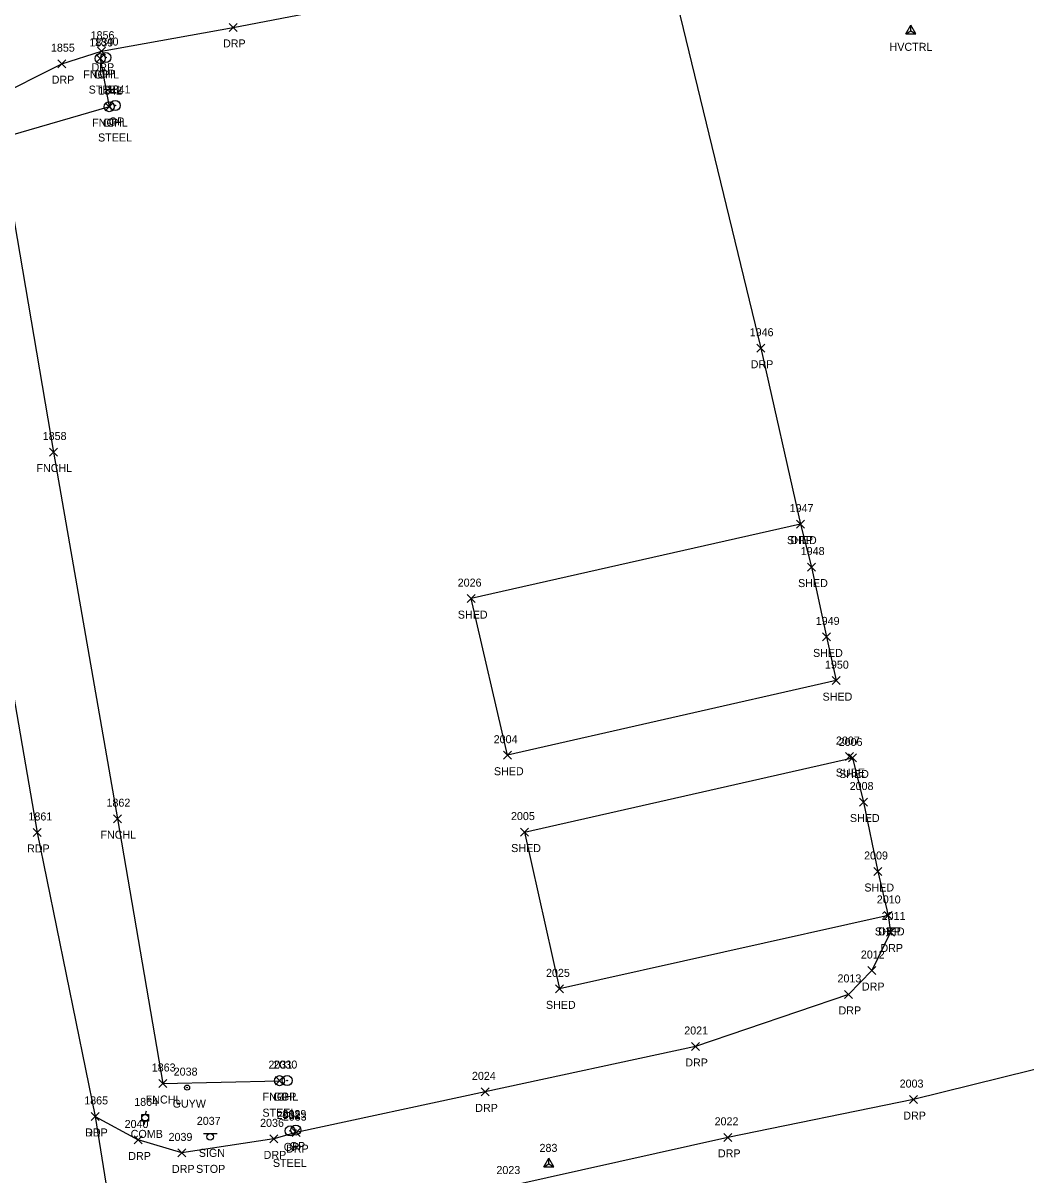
# Model space of a CAD drawing. Extents: x 1481523 to 1489083, y 884156 to 893756.
# Drawn here: x 1486651.1 to 1486901.6, y 888166.7 to 888454.5 of the extents above; entities that cross this region are included whole.
import ezdxf

# ---------------------------------------------------------------- set-up
doc = ezdxf.new("R2010")
doc.units = 0
for name, color, linetype in [('C_A', 7, 'Continuous'), ('C_I', 7, 'Continuous'), ('CPSM', 7, 'Continuous'), ('L_A', 7, 'Continuous'), ('L_I', 7, 'Continuous'), ('L_TIC', 7, 'Continuous'), ('LBC', 7, 'Continuous'), ('LFNC', 7, 'Continuous'), ('P_A', 7, 'Continuous'), ('P_I', 7, 'Continuous'), ('P_TIC', 7, 'Continuous'), ('PET', 7, 'Continuous'), ('R_A', 7, 'Continuous'), ('R_C', 7, 'Continuous'), ('R_I', 7, 'Continuous'), ('R_TIC', 7, 'Continuous'), ('RDP', 7, 'Continuous'), ('RGP', 7, 'Continuous'), ('S_A', 7, 'Continuous'), ('S_C', 7, 'Continuous'), ('S_I', 7, 'Continuous'), ('SSGN', 7, 'Continuous'), ('U_A', 7, 'Continuous'), ('U_I', 7, 'Continuous'), ('U_TIC', 7, 'Continuous'), ('UP', 7, 'Continuous'), ('UPGW', 7, 'Continuous')]:
    doc.layers.add(name, color=color, linetype=linetype)

msp = doc.modelspace()

# ---------------------------------------------------------------- linework, layer by layer
at = {"layer": 'CPSM'}
for p, q in [((1486871.57, 888451.78), (1486872.82, 888453.95)), ((1486874.07, 888451.78), (1486872.82, 888453.95)), ((1486872.82, 888452.51), (1486872.82, 888453.95)), ((1486871.57, 888451.78), (1486872.82, 888452.51)), ((1486871.57, 888451.78), (1486874.07, 888451.78)), ((1486872.82, 888452.51), (1486872.82, 888452.51)), ((1486872.82, 888452.51), (1486874.07, 888451.78)), ((1486781.2, 888168.7), (1486782.45, 888170.86)), ((1486783.7, 888168.7), (1486782.45, 888170.86)), ((1486782.45, 888169.42), (1486782.45, 888170.86)), ((1486781.2, 888168.7), (1486782.45, 888169.42)), ((1486781.2, 888168.7), (1486783.7, 888168.7)), ((1486782.45, 888169.42), (1486782.45, 888169.42)), ((1486782.45, 888169.42), (1486783.7, 888168.7))]:
    msp.add_line(p, q, dxfattribs=at)
at = {"layer": 'L_TIC'}
for points in [[(1486669.36, 888444.6), (1486671.36, 888446.6)], [(1486671.36, 888444.6), (1486669.36, 888446.6)], [(1486671.6, 888432.56), (1486673.6, 888434.56)], [(1486673.6, 888432.56), (1486671.6, 888434.56)], [(1486657.68, 888346.28), (1486659.68, 888348.28)], [(1486659.68, 888346.28), (1486657.68, 888348.28)], [(1486844.25, 888328.26), (1486846.25, 888330.26)], [(1486846.25, 888328.26), (1486844.25, 888330.26)], [(1486844.25, 888328.26), (1486846.25, 888330.26)], [(1486846.25, 888328.26), (1486844.25, 888330.26)], [(1486847.03, 888317.53), (1486849.03, 888319.53)], [(1486849.03, 888317.53), (1486847.03, 888319.53)], [(1486762.04, 888309.65), (1486764.04, 888311.65)], [(1486764.04, 888309.65), (1486762.04, 888311.65)], [(1486762.04, 888309.65), (1486764.04, 888311.65)], [(1486764.04, 888309.65), (1486762.04, 888311.65)], [(1486850.78, 888300.08), (1486852.78, 888302.08)], [(1486852.78, 888300.08), (1486850.78, 888302.08)], [(1486853.16, 888289.15), (1486855.16, 888291.15)], [(1486855.16, 888289.15), (1486853.16, 888291.15)], [(1486771.06, 888270.52), (1486773.06, 888272.52)], [(1486773.06, 888270.52), (1486771.06, 888272.52)], [(1486857.29, 888269.84), (1486859.29, 888271.84)], [(1486859.29, 888269.84), (1486857.29, 888271.84)], [(1486859.98, 888258.83), (1486861.98, 888260.83)], [(1486861.98, 888258.83), (1486859.98, 888260.83)], [(1486673.66, 888254.66), (1486675.66, 888256.66)], [(1486675.66, 888254.66), (1486673.66, 888256.66)], [(1486775.37, 888251.32), (1486777.37, 888253.32)], [(1486777.37, 888251.32), (1486775.37, 888253.32)], [(1486775.37, 888251.32), (1486777.37, 888253.32)], [(1486777.37, 888251.32), (1486775.37, 888253.32)], [(1486863.58, 888241.47), (1486865.58, 888243.47)], [(1486865.58, 888241.47), (1486863.58, 888243.47)], [(1486866.2, 888230.49), (1486868.2, 888232.49)], [(1486868.2, 888230.49), (1486866.2, 888232.49)], [(1486784.05, 888212.15), (1486786.05, 888214.15)], [(1486786.05, 888212.15), (1486784.05, 888214.15)], [(1486784.05, 888212.15), (1486786.05, 888214.15)], [(1486786.05, 888212.15), (1486784.05, 888214.15)], [(1486714.15, 888189.21), (1486716.15, 888191.21)], [(1486716.15, 888189.21), (1486714.15, 888191.21)], [(1486684.97, 888188.5), (1486686.97, 888190.5)], [(1486686.97, 888188.5), (1486684.97, 888190.5)]]:
    msp.add_lwpolyline(points, dxfattribs=at)
at = {"layer": 'LBC'}
for points in [[(1486845.25, 888329.26), (1486848.03, 888318.53), (1486851.78, 888301.08), (1486854.16, 888290.15), (1486772.06, 888271.52), (1486763.04, 888310.65)], [(1486845.25, 888329.26), (1486763.04, 888310.65)], [(1486776.37, 888252.32), (1486858.29, 888270.84), (1486860.98, 888259.83), (1486864.58, 888242.47), (1486867.2, 888231.49), (1486785.05, 888213.15)], [(1486776.37, 888252.32), (1486785.05, 888213.15)]]:
    msp.add_lwpolyline(points, dxfattribs=at)
at = {"layer": 'LFNC'}
msp.add_lwpolyline([(1486670.36, 888445.6), (1486672.6, 888433.56), (1486645.27, 888425.57), (1486658.68, 888347.28), (1486674.66, 888255.66), (1486685.97, 888189.5), (1486715.15, 888190.21)], dxfattribs=at)
at = {"layer": 'P_TIC'}
for points in [[(1486653.61, 888251.22), (1486655.61, 888253.22)], [(1486655.61, 888251.22), (1486653.61, 888253.22)], [(1486668.1, 888180.27), (1486670.1, 888182.27)], [(1486670.1, 888180.27), (1486668.1, 888182.27)]]:
    msp.add_lwpolyline(points, dxfattribs=at)
at = {"layer": 'PET'}
msp.add_lwpolyline([(1486482.46, 889213.8), (1486493.22, 889156.8), (1486512.17, 889057.76), (1486527.58, 888974.51), (1486542.53, 888889.08), (1486553.79, 888825.37), (1486565.07, 888760.91), (1486577.19, 888690.78), (1486591.4, 888610.57), (1486602.78, 888547.25), (1486614.23, 888481.5), (1486627.06, 888409.28), (1486638.94, 888342.58), (1486654.61, 888252.22), (1486669.1, 888181.27), (1486680.17, 888112.03), (1486680.99, 888105.73)], dxfattribs=at)
at = {"layer": 'R_TIC'}
for points in [[(1486702.54, 888452.36), (1486704.54, 888454.36)], [(1486704.54, 888452.36), (1486702.54, 888454.36)], [(1486669.7, 888446.41), (1486671.7, 888448.41)], [(1486671.7, 888446.41), (1486669.7, 888448.41)], [(1486659.74, 888443.3), (1486661.74, 888445.3)], [(1486661.74, 888443.3), (1486659.74, 888445.3)], [(1486834.34, 888372.21), (1486836.34, 888374.21)], [(1486836.34, 888372.21), (1486834.34, 888374.21)], [(1486844.25, 888328.26), (1486846.25, 888330.26)], [(1486846.25, 888328.26), (1486844.25, 888330.26)], [(1486866.2, 888230.49), (1486868.2, 888232.49)], [(1486868.2, 888230.49), (1486866.2, 888232.49)], [(1486866.75, 888226.35), (1486868.75, 888228.35)], [(1486868.75, 888226.35), (1486866.75, 888228.35)], [(1486862.12, 888216.72), (1486864.12, 888218.72)], [(1486864.12, 888216.72), (1486862.12, 888218.72)], [(1486856.29, 888210.76), (1486858.29, 888212.76)], [(1486858.29, 888210.76), (1486856.29, 888212.76)], [(1486818.01, 888197.75), (1486820.01, 888199.75)], [(1486820.01, 888197.75), (1486818.01, 888199.75)], [(1486765.54, 888186.41), (1486767.54, 888188.41)], [(1486767.54, 888186.41), (1486765.54, 888188.41)], [(1486872.46, 888184.48), (1486874.46, 888186.48)], [(1486874.46, 888184.48), (1486872.46, 888186.48)], [(1486668.1, 888180.27), (1486670.1, 888182.27)], [(1486670.1, 888180.27), (1486668.1, 888182.27)], [(1486712.68, 888174.67), (1486714.68, 888176.67)], [(1486714.68, 888174.67), (1486712.68, 888176.67)], [(1486718.3, 888176.23), (1486720.3, 888178.23)], [(1486720.3, 888176.23), (1486718.3, 888178.23)], [(1486826.16, 888175.05), (1486828.16, 888177.05)], [(1486828.16, 888175.05), (1486826.16, 888177.05)], [(1486678.87, 888174.39), (1486680.87, 888176.39)], [(1486680.87, 888174.39), (1486678.87, 888176.39)], [(1486678.87, 888174.39), (1486680.87, 888176.39)], [(1486680.87, 888174.39), (1486678.87, 888176.39)], [(1486689.78, 888171.16), (1486691.78, 888173.16)], [(1486691.78, 888171.16), (1486689.78, 888173.16)]]:
    msp.add_lwpolyline(points, dxfattribs=at)
at = {"layer": 'RDP'}
for points in [[(1486627.06, 888409.28), (1486634.2, 888424.78), (1486643.14, 888435.44), (1486660.74, 888444.3), (1486670.7, 888447.41), (1486703.54, 888453.36), (1486762.17, 888464.63), (1486810.87, 888474.09), (1486835.34, 888373.21), (1486845.25, 888329.26)], [(1486959.85, 888365.95), (1486963.01, 888350.2), (1486966.58, 888328.39), (1486977.82, 888267.82), (1486986.38, 888222.13), (1486988.25, 888212.61), (1486961.42, 888207.24), (1486873.46, 888185.48), (1486827.16, 888176.05), (1486772.66, 888163.88), (1486723.25, 888154.26), (1486717.91, 888152.68), (1486701.43, 888143.32), (1486693.75, 888134.74)], [(1486867.2, 888231.49), (1486867.75, 888227.35), (1486863.12, 888217.72), (1486857.29, 888211.76), (1486819.01, 888198.75), (1486766.54, 888187.41), (1486719.3, 888177.23), (1486713.68, 888175.67), (1486690.78, 888172.16), (1486679.87, 888175.39)], [(1486669.1, 888181.27), (1486679.87, 888175.39)]]:
    msp.add_lwpolyline(points, dxfattribs=at)
at = {"layer": 'RGP'}
for p, q in [((1486670.36, 888445.6), (1486670.36, 888445.6)), ((1486671.75, 888445.83), (1486671.75, 888445.83)), ((1486672.6, 888433.56), (1486672.6, 888433.56)), ((1486674.09, 888433.86), (1486674.09, 888433.86)), ((1486715.15, 888190.21), (1486715.15, 888190.21)), ((1486717.06, 888190.23), (1486717.06, 888190.23)), ((1486717.77, 888177.66), (1486717.77, 888177.66)), ((1486719.24, 888177.88), (1486719.24, 888177.88))]:
    msp.add_line(p, q, dxfattribs=at)
for centre, radius in [((1486670.36, 888445.6), 1.25), ((1486670.36, 888445.6), 0.0833), ((1486671.75, 888445.83), 1.25), ((1486671.75, 888445.83), 0.0833), ((1486672.6, 888433.56), 1.25), ((1486672.6, 888433.56), 0.0833), ((1486674.09, 888433.86), 1.25), ((1486674.09, 888433.86), 0.0833), ((1486715.15, 888190.21), 1.25), ((1486717.06, 888190.23), 1.25), ((1486715.15, 888190.21), 0.0833), ((1486717.06, 888190.23), 0.0833), ((1486717.77, 888177.66), 1.25), ((1486717.77, 888177.66), 0.0833), ((1486719.24, 888177.88), 1.25), ((1486719.24, 888177.88), 0.0833)]:
    msp.add_circle(centre, radius, dxfattribs=at)
at = {"layer": 'SSGN'}
for p, q in [((1486696.19, 888177.02), (1486699.53, 888177.02)), ((1486697.84, 888176.19), (1486697.84, 888176.19))]:
    msp.add_line(p, q, dxfattribs=at)
msp.add_circle((1486697.84, 888176.19), 0.833, dxfattribs=at)
at = {"layer": 'U_TIC'}
for points in [[(1486856.54, 888270.19), (1486858.54, 888272.19)], [(1486858.54, 888270.19), (1486856.54, 888272.19)]]:
    msp.add_lwpolyline(points, dxfattribs=at)
at = {"layer": 'UP'}
for p, q in [((1486681.84, 888182.57), (1486681.59, 888181.74)), ((1486680.75, 888180.07), (1486680.75, 888181.74)), ((1486680.75, 888181.74), (1486682.42, 888181.74)), ((1486682.42, 888180.07), (1486680.75, 888180.07)), ((1486681.34, 888179.24), (1486681.59, 888180.07)), ((1486681.59, 888180.91), (1486681.59, 888180.91)), ((1486682.42, 888181.74), (1486682.42, 888180.07))]:
    msp.add_line(p, q, dxfattribs=at)
msp.add_circle((1486681.59, 888180.91), 0.833, dxfattribs=at)
at = {"layer": 'UPGW'}
for radius in [0.625, 0.0833]:
    msp.add_circle((1486692.05, 888188.47), radius, dxfattribs=at)

# ---------------------------------------------------------------- texts
at = {"layer": 'C_A'}
msp.add_text('HVCTRL', height=2, dxfattribs=at).set_placement((1486867.52, 888447.51))
at = {"layer": 'C_I'}
msp.add_text('283', height=2, dxfattribs=at).set_placement((1486780.09, 888172.42))
at = {"layer": 'L_A'}
for s, p in [('FNCHL', (1486666.11, 888440.6)), ('FNCHL', (1486668.34, 888428.56)), ('FNCHL', (1486654.43, 888342.28)), ('SHED', (1486841.89, 888324.26)), ('SHED', (1486841.89, 888324.26)), ('SHED', (1486844.67, 888313.53)), ('SHED', (1486759.68, 888305.65)), ('SHED', (1486759.68, 888305.65)), ('SHED', (1486848.41, 888296.08)), ('SHED', (1486850.79, 888285.15)), ('SHED', (1486768.7, 888266.52)), ('SHED', (1486854.92, 888265.84)), ('SHED', (1486857.62, 888254.83)), ('FNCHL', (1486670.41, 888250.66)), ('SHED', (1486773.01, 888247.32)), ('SHED', (1486773.01, 888247.32)), ('SHED', (1486861.22, 888237.47)), ('SHED', (1486863.84, 888226.49)), ('SHED', (1486781.69, 888208.15)), ('SHED', (1486781.69, 888208.15)), ('FNCHL', (1486681.72, 888184.5)), ('FNCHL', (1486710.9, 888185.21))]:
    msp.add_text(s, height=2, dxfattribs=at).set_placement(p)
at = {"layer": 'L_I'}
for s, p in [('1839', (1486667.66, 888448.6)), ('1842', (1486669.9, 888436.56)), ('1858', (1486655.99, 888350.28)), ('1947', (1486842.56, 888332.26)), ('1947', (1486842.56, 888332.26)), ('1948', (1486845.34, 888321.53)), ('2026', (1486759.65, 888313.65)), ('2026', (1486759.65, 888313.65)), ('1949', (1486849.08, 888304.08)), ('1950', (1486851.38, 888293.15)), ('2004', (1486768.64, 888274.52)), ('2006', (1486854.81, 888273.84)), ('2008', (1486857.56, 888262.83)), ('1862', (1486671.92, 888258.66)), ('2005', (1486772.96, 888255.32)), ('2005', (1486772.96, 888255.32)), ('2009', (1486861.16, 888245.47)), ('2010', (1486864.34, 888234.49)), ('2025', (1486781.71, 888216.15)), ('2025', (1486781.71, 888216.15)), ('1863', (1486683.23, 888192.5)), ('2031', (1486712.38, 888193.21))]:
    msp.add_text(s, height=2, dxfattribs=at).set_placement(p)
at = {"layer": 'P_A'}
for p in [(1486652.09, 888247.22), (1486666.59, 888176.27)]:
    msp.add_text('RDP', height=2, dxfattribs=at).set_placement(p)
at = {"layer": 'P_I'}
for s, p in [('1861', (1486652.43, 888255.22)), ('1865', (1486666.36, 888184.27))]:
    msp.add_text(s, height=2, dxfattribs=at).set_placement(p)
at = {"layer": 'R_A'}
for s, p in [('DRP', (1486701.03, 888448.36)), ('DRP', (1486668.19, 888442.41)), ('GP', (1486668.8, 888440.6)), ('GP', (1486670.19, 888440.83)), ('DRP', (1486658.23, 888439.3)), ('GP', (1486671.03, 888428.56)), ('GP', (1486672.52, 888428.86)), ('DRP', (1486832.83, 888368.21)), ('DRP', (1486842.74, 888324.26)), ('DRP', (1486864.69, 888226.49)), ('DRP', (1486865.24, 888222.35)), ('DRP', (1486860.61, 888212.72)), ('DRP', (1486854.78, 888206.76)), ('DRP', (1486816.5, 888193.75)), ('GP', (1486713.59, 888185.21)), ('GP', (1486715.49, 888185.23)), ('DRP', (1486764.03, 888182.41)), ('DRP', (1486870.95, 888180.48)), ('DRP', (1486666.59, 888176.27)), ('GP', (1486716.2, 888172.66)), ('DRP', (1486716.78, 888172.23)), ('GP', (1486717.67, 888172.88)), ('DRP', (1486677.36, 888170.39)), ('DRP', (1486677.36, 888170.39)), ('DRP', (1486711.17, 888170.67)), ('DRP', (1486824.65, 888171.05)), ('DRP', (1486688.27, 888167.16))]:
    msp.add_text(s, height=2, dxfattribs=at).set_placement(p)
at = {"layer": 'R_C'}
for p in [(1486667.47, 888436.83), (1486669.81, 888424.86), (1486710.87, 888181.21), (1486713.49, 888168.66)]:
    msp.add_text('STEEL', height=2, dxfattribs=at).set_placement(p)
at = {"layer": 'R_I'}
for s, p in [('1839', (1486667.66, 888448.6)), ('1856', (1486667.95, 888450.41)), ('1840', (1486668.97, 888448.83)), ('1855', (1486658.05, 888447.3)), ('1842', (1486669.9, 888436.56)), ('1841', (1486671.96, 888436.86)), ('1946', (1486832.59, 888376.21)), ('1947', (1486842.56, 888332.26)), ('2010', (1486864.34, 888234.49)), ('2011', (1486865.55, 888230.35)), ('2012', (1486860.35, 888220.72)), ('2013', (1486854.52, 888214.76)), ('2021', (1486816.24, 888201.75)), ('2031', (1486712.38, 888193.21)), ('2030', (1486713.63, 888193.23)), ('2024', (1486763.21, 888190.41)), ('2003', (1486870.04, 888188.48)), ('1865', (1486666.36, 888184.27)), ('2032', (1486714.43, 888180.66)), ('2029', (1486715.89, 888180.88)), ('2040', (1486676.45, 888178.39)), ('2040', (1486676.45, 888178.39)), ('2036', (1486710.29, 888178.67)), ('2033', (1486715.96, 888180.23)), ('2022', (1486823.82, 888179.05)), ('2039', (1486687.43, 888175.16)), ('2023', (1486769.32, 888166.88))]:
    msp.add_text(s, height=2, dxfattribs=at).set_placement(p)
at = {"layer": 'S_A'}
msp.add_text('SIGN', height=2, dxfattribs=at).set_placement((1486694.98, 888171.17))
at = {"layer": 'S_C'}
msp.add_text('STOP', height=2, dxfattribs=at).set_placement((1486694.3, 888167.17))
at = {"layer": 'S_I'}
msp.add_text('2037', height=2, dxfattribs=at).set_placement((1486694.48, 888179.17))
at = {"layer": 'U_A'}
for s, p in [('SUBE', (1486854.08, 888266.19)), ('GUYW', (1486688.44, 888183.47)), ('COMB', (1486677.97, 888175.91))]:
    msp.add_text(s, height=2, dxfattribs=at).set_placement(p)
at = {"layer": 'U_I'}
for s, p in [('2007', (1486854.13, 888274.19)), ('2038', (1486688.71, 888191.47)), ('1864', (1486678.85, 888183.91))]:
    msp.add_text(s, height=2, dxfattribs=at).set_placement(p)

doc.saveas('drawing.dxf')
